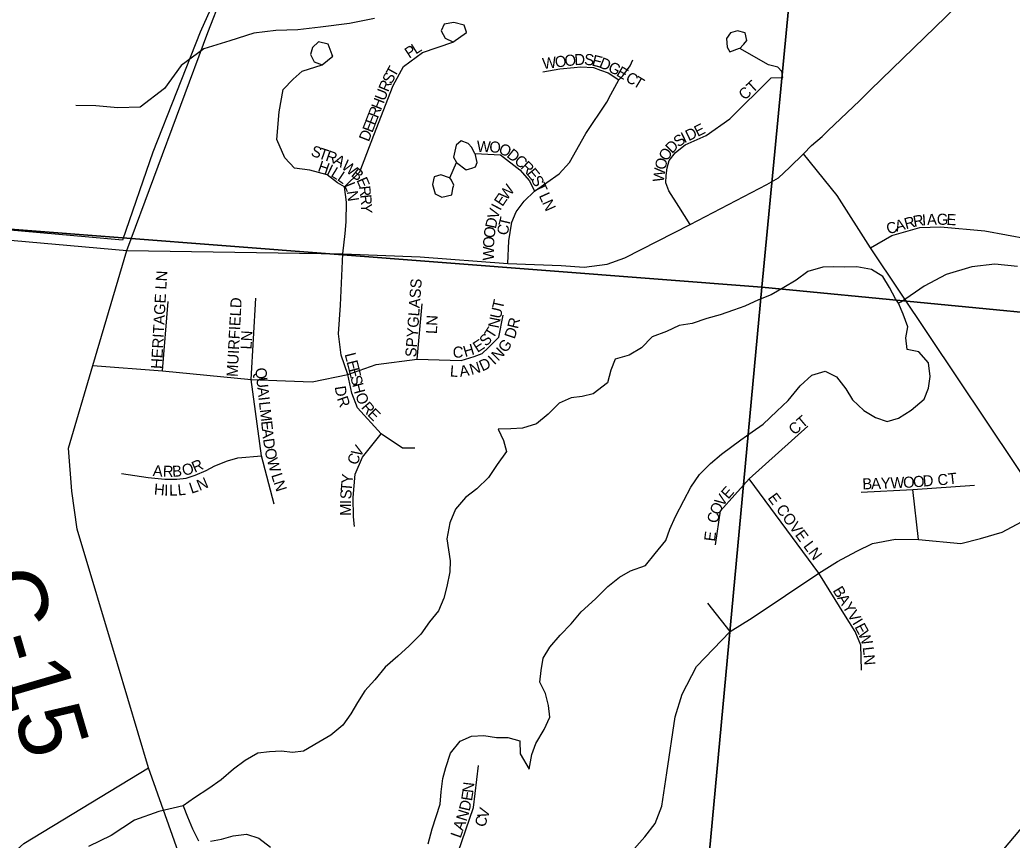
# Model space of a CAD drawing. Extents: x 0 to 1064, y 0 to 440.
# Drawn here: x 172.51 to 186.14, y 107.1 to 118.36 of the extents above; entities that cross this region are included whole.
import ezdxf

# ---------------------------------------------------------------- set-up
doc = ezdxf.new("R2010")
doc.units = 0
for name, color, linetype in [('GM_X_Corporation', 7, 'Continuous'), ('GM_X_County_Road', 7, 'Continuous'), ('GM_X_County_Road_Text', 7, 'Continuous'), ('GM_X_County_Subdivision', 7, 'Continuous'), ('GM_X_Minor_Lake', 7, 'Continuous'), ('GM_X_Minor_River', 7, 'Continuous'), ('GM_X_Section', 7, 'Continuous'), ('GM_X_Township_Road', 7, 'Continuous'), ('GM_X_Township_Subdivision', 7, 'Continuous'), ('GM_X_Township_Subdivision_Text', 7, 'Continuous')]:
    doc.layers.add(name, color=color, linetype=linetype)

msp = doc.modelspace()

# ---------------------------------------------------------------- linework, layer by layer
at = {"layer": 'GM_X_Corporation'}
msp.add_lwpolyline([(176.201, 124.373), (175.606, 119.781), (175.563, 119.506), (175.5, 119.337), (174.988, 118.195), (174.334, 116.544), (173.92, 115.338), (167.075, 115.945), (167.031, 124.73)], dxfattribs=at)
at = {"layer": 'GM_X_County_Road'}
for points in [[(173.981, 115.194), (175.091, 118.189), (175.485, 119.201), (175.565, 119.396)], [(184.2, 117.4), (185.384, 118.549), (185.551, 118.614), (185.847, 118.632), (186.762, 118.52)], [(173.981, 115.194), (176.948, 115.149), (178.012, 115.109), (179.214, 115.015), (179.948, 114.99), (180.263, 114.965), (180.578, 115.008), (180.823, 115.095), (181.719, 115.554), (182.773, 116.1), (182.932, 116.194), (183.084, 116.335), (183.279, 116.523), (183.388, 116.639), (183.533, 116.76), (183.612, 116.837), (183.702, 116.925), (184.045, 117.251), (184.2, 117.4)], [(167.01, 115.771), (170.217, 115.528), (170.761, 115.48), (171.241, 115.437), (173.981, 115.194)], [(173.849, 109.519), (173.297, 111.368), (173.224, 111.89), (173.175, 112.478), (173.513, 113.616), (173.981, 115.194)], [(175.37, 105.001), (174.275, 108.09), (173.849, 109.519)]]:
    msp.add_lwpolyline(points, dxfattribs=at)
at = {"layer": 'GM_X_County_Subdivision'}
msp.add_lwpolyline([(184.113, 102.985), (183.905, 103.57), (183.808, 103.968), (183.917, 104.451), (184.17, 104.765), (186.47, 107.493), (186.741, 108.41), (186.813, 109.014), (186.958, 109.859), (186.958, 110.402), (186.599, 111.646), (184.198, 115.23), (183.742, 115.95), (183.279, 116.523)], dxfattribs=at)
at = {"layer": 'GM_X_Minor_Lake'}
for points in [[(184.582, 114.473), (184.54, 114.533), (184.461, 114.685), (184.369, 114.837), (184.211, 114.934), (184.011, 114.971), (183.847, 114.965), (183.695, 114.971), (183.543, 114.965), (183.336, 114.904), (183.178, 114.788), (183.008, 114.685), (182.831, 114.588), (182.661, 114.515), (182.473, 114.43), (182.315, 114.375), (182.132, 114.309), (181.95, 114.26), (181.749, 114.193), (181.567, 114.163), (181.397, 114.084), (181.196, 114.011), (181.05, 113.859), (180.88, 113.756), (180.691, 113.701), (180.631, 113.549), (180.582, 113.379), (180.388, 113.227), (180.236, 113.191), (180.084, 113.173), (179.919, 113.1), (179.767, 112.948), (179.609, 112.814), (179.415, 112.754), (179.257, 112.747), (179.08, 112.741), (179.153, 112.583), (179.196, 112.432), (179.068, 112.255), (178.947, 112.079), (178.789, 111.921), (178.631, 111.8), (178.497, 111.642), (178.418, 111.454), (178.376, 111.235), (178.424, 110.931), (178.418, 110.779), (178.376, 110.579), (178.333, 110.421), (178.26, 110.245), (178.139, 110.093), (178.017, 109.923), (177.859, 109.765), (177.701, 109.625), (177.531, 109.473), (177.385, 109.297), (177.251, 109.145), (177.148, 108.987), (177.057, 108.829), (176.947, 108.677), (176.783, 108.538), (176.619, 108.44), (176.406, 108.319), (176.254, 108.301), (176.102, 108.319), (175.938, 108.307), (175.78, 108.289), (175.604, 108.191), (175.446, 108.07), (175.276, 107.924), (175.105, 107.803), (174.911, 107.675), (174.753, 107.566), (174.814, 107.414)], [(178.121, 107.043), (178.176, 107.25), (178.285, 107.59), (178.297, 107.76), (178.322, 107.942), (178.364, 108.094), (178.425, 108.289), (178.559, 108.453), (178.717, 108.525), (178.887, 108.532), (179.057, 108.507), (179.215, 108.507), (179.379, 108.459), (179.386, 108.282), (179.507, 108.07), (179.544, 108.27), (179.598, 108.422), (179.714, 108.617), (179.793, 108.787), (179.775, 108.945), (179.732, 109.109), (179.653, 109.267), (179.671, 109.425), (179.701, 109.595), (179.793, 109.746), (179.932, 109.911), (180.084, 110.068), (180.224, 110.232), (180.419, 110.409), (180.589, 110.579), (180.747, 110.706), (180.899, 110.797), (181.106, 110.87), (181.239, 111.034), (181.385, 111.211), (181.44, 111.368), (181.519, 111.539), (181.634, 111.763), (181.731, 111.946), (181.847, 112.116), (181.999, 112.267), (182.151, 112.395), (182.418, 112.596), (182.57, 112.705), (182.722, 112.808), (182.911, 112.99), (183.069, 113.136), (183.233, 113.337), (183.391, 113.482), (183.573, 113.537), (183.731, 113.458), (183.859, 113.294), (183.95, 113.142), (184.108, 112.996), (184.267, 112.899), (184.425, 112.845), (184.583, 112.893), (184.759, 113.002), (184.935, 113.154), (184.996, 113.306), (185.02, 113.464), (184.996, 113.652), (184.862, 113.804), (184.704, 113.835), (184.686, 113.993), (184.71, 114.145), (184.649, 114.321), (184.582, 114.473)], [(174.814, 107.414), (174.881, 107.25), (174.966, 107.086)], [(175.13, 107.08), (175.282, 107.11), (175.44, 107.153), (175.622, 107.177), (175.793, 107.122), (175.951, 107.001)]]:
    msp.add_lwpolyline(points, dxfattribs=at)
at = {"layer": 'GM_X_Minor_River'}
for points in [[(177.383, 118.379), (177.037, 118.312), (176.641, 118.263), (176.331, 118.227), (176.027, 118.215), (175.723, 118.178), (175.395, 118.075), (175.036, 117.966), (174.726, 117.735), (174.495, 117.419), (174.161, 117.164), (173.857, 117.152), (173.553, 117.182), (173.28, 117.188)], [(186.218, 114.977), (185.908, 115.007), (185.592, 114.971), (185.239, 114.867), (184.935, 114.703), (184.625, 114.491), (184.582, 114.473)], [(174.753, 107.566), (174.419, 107.487), (174.084, 107.371), (173.762, 107.159), (173.452, 107.007)]]:
    msp.add_lwpolyline(points, dxfattribs=at)
at = {"layer": 'GM_X_Section'}
for points in [[(168.142, 132.406), (184.27, 131.039), (182.704, 114.691), (166.556, 115.937)], [(184.27, 131.039), (200.029, 129.432), (198.641, 113.153), (182.704, 114.691)], [(166.556, 115.937), (182.704, 114.691), (180.995, 96.285), (164.917, 99.233)]]:
    msp.add_lwpolyline(points, close=True, dxfattribs=at)
msp.add_lwpolyline([(196.734, 94.569), (180.995, 96.285), (182.704, 114.691), (198.641, 113.153)], dxfattribs=at)
at = {"layer": 'GM_X_Township_Road'}
msp.add_lwpolyline([(167.948, 105.244), (168.32, 105.412), (169.431, 105.913), (170.031, 106.261), (170.509, 106.374), (171.357, 106.524), (171.637, 106.492), (171.819, 106.52), (172.115, 106.652), (172.565, 107.051), (174.275, 108.09)], dxfattribs=at)
at = {"layer": 'GM_X_Township_Subdivision'}
for points in [[(178.645, 118.192), (178.616, 118.291), (178.473, 118.327), (178.34, 118.305), (178.299, 118.213), (178.355, 118.113), (178.457, 118.061)], [(176.971, 116.07), (177.181, 116.276), (177.371, 116.779), (177.639, 117.459), (177.783, 117.723), (178.043, 117.913), (178.46, 118.058), (178.646, 118.187), (178.645, 118.192)], [(182.448, 118.021), (182.456, 118.03), (182.498, 118.078), (182.474, 118.184), (182.371, 118.211), (182.273, 118.185), (182.219, 118.107), (182.227, 117.986), (182.267, 117.925), (182.4, 117.972)], [(176.802, 117.879), (176.801, 117.882), (176.747, 118.027), (176.612, 118.059), (176.529, 117.981), (176.501, 117.886), (176.551, 117.785), (176.661, 117.745)], [(181.719, 115.554), (181.566, 115.797), (181.427, 116.012), (181.384, 116.123), (181.39, 116.226), (181.404, 116.328), (181.43, 116.431), (181.519, 116.539), (181.651, 116.646), (181.938, 116.775), (182.266, 117.003), (182.832, 117.566), (182.994, 117.569), (182.978, 117.655), (182.924, 117.715), (182.797, 117.744), (182.403, 117.969), (182.448, 118.021)], [(176.948, 115.149), (176.977, 115.427), (176.995, 115.59), (176.999, 115.858), (176.971, 116.07), (176.872, 116.123), (176.731, 116.235), (176.492, 116.296), (176.282, 116.325), (176.152, 116.468), (176.039, 116.717), (176.072, 117.097), (176.125, 117.406), (176.266, 117.546), (176.389, 117.657), (176.664, 117.745), (176.808, 117.863), (176.802, 117.879)], [(179.695, 117.648), (179.93, 117.688), (180.127, 117.708)], [(180.127, 117.708), (180.214, 117.717), (180.391, 117.706), (180.489, 117.67), (180.592, 117.636), (180.738, 117.538)], [(180.631, 117.338), (180.738, 117.538), (180.793, 117.596), (180.896, 117.73), (180.93, 117.813)], [(179.214, 115.015), (179.229, 115.326), (179.268, 115.583), (179.33, 115.728), (179.438, 115.872), (179.583, 116.01), (179.919, 116.248), (180.06, 116.404), (180.288, 116.8), (180.574, 117.23), (180.631, 117.338)], [(178.672, 116.662), (178.671, 116.663), (178.572, 116.7), (178.504, 116.641), (178.469, 116.478), (178.509, 116.405), (178.641, 116.303), (178.686, 116.317)], [(178.762, 116.525), (178.716, 116.614), (178.672, 116.662)], [(178.686, 116.317), (178.721, 116.327), (178.769, 116.342), (178.795, 116.402), (178.765, 116.525), (179.114, 116.509), (179.379, 116.303), (179.512, 116.153), (179.583, 116.01)], [(178.461, 116.047), (178.461, 116.05), (178.471, 116.094), (178.442, 116.162), (178.416, 116.193), (178.509, 116.405)], [(178.413, 116.193), (178.292, 116.233), (178.2, 116.205), (178.179, 116.102), (178.218, 115.973), (178.308, 115.928), (178.443, 115.961), (178.461, 116.047)], [(184.198, 115.23), (184.492, 115.399), (184.874, 115.509), (185.16, 115.519), (185.771, 115.465), (186.365, 115.355), (186.562, 115.333), (186.734, 115.369), (186.91, 115.502), (187.28, 115.664), (187.415, 115.719), (187.586, 115.744), (187.983, 115.792), (188.366, 115.815), (188.725, 115.818), (189.012, 115.796), (189.38, 115.686), (189.833, 115.411), (190.245, 115.132), (190.498, 114.875), (190.638, 114.676), (190.843, 114.542), (191.143, 114.451), (192.172, 114.458)], [(177.936, 112.479), (177.769, 112.479), (177.472, 112.678), (177.148, 113.032), (177.07, 113.236), (177.018, 113.492), (176.924, 113.758), (176.887, 114.05), (176.913, 114.442), (176.948, 115.149)], [(174.471, 113.544), (174.548, 114.496)], [(175.687, 113.424), (175.751, 114.541)], [(177.968, 113.701), (178.037, 114.462)], [(173.513, 113.616), (174.471, 113.544), (175.687, 113.424), (176.158, 113.404), (176.527, 113.393), (177.018, 113.492), (177.404, 113.627), (177.968, 113.701), (178.573, 113.685), (178.75, 113.737), (178.86, 113.779), (178.944, 113.857), (179.091, 114.002), (179.152, 114.306)], [(176.005, 111.712), (175.828, 112.375), (175.687, 113.424)], [(182.07, 111.15), (182.137, 111.621), (182.529, 112.057), (183.337, 112.78)], [(177.108, 111.403), (177.092, 111.538), (177.091, 111.801), (177.117, 112.124), (177.216, 112.354), (177.472, 112.678)], [(173.907, 112.132), (174.274, 112.077), (174.499, 112.056), (174.667, 112.055), (174.794, 112.067), (174.919, 112.109), (175.067, 112.174), (175.189, 112.237), (175.363, 112.307), (175.505, 112.347), (175.828, 112.375)], [(183.486, 110.765), (182.529, 112.057)], [(184.072, 111.875), (184.78, 111.912), (185.628, 111.973)], [(184.859, 111.227), (184.78, 111.912)], [(180.881, 106.897), (181.097, 107.139), (181.238, 107.325), (181.329, 107.561), (181.399, 108.019), (181.515, 108.788), (181.61, 109.1), (181.806, 109.483), (182.269, 109.96), (182.571, 110.151), (183.486, 110.765), (183.743, 110.921), (184.009, 111.067), (184.226, 111.172), (184.542, 111.228), (184.859, 111.227), (185.438, 111.172), (185.709, 111.238), (186.006, 111.328), (186.273, 111.469)], [(183.856, 110.174), (183.486, 110.765)], [(182.269, 109.96), (181.961, 110.35)], [(184.075, 109.431), (184.064, 109.772), (183.989, 109.961), (183.856, 110.174)], [(178.537, 106.308), (178.531, 106.931), (178.742, 107.542), (178.813, 108.123)]]:
    msp.add_lwpolyline(points, dxfattribs=at)

# ---------------------------------------------------------------- texts
at = {"layer": 'GM_X_County_Road_Text'}
msp.add_text('C-15', height=0.9091, rotation=286.3705, dxfattribs=at).set_placement((171.868, 110.691))
at = {"layer": 'GM_X_Township_Subdivision_Text'}
for s, height, rotation, p in [('P', 0.152, 33.4476, (177.86, 117.827)), ('L', 0.152, 32.3036, (177.949, 117.885)), ('W', 0.152, 7.1125, (179.699, 117.685)), ('O', 0.152, 7.1006, (179.871, 117.706)), ('O', 0.152, 7.0973, (180.003, 117.723)), ('D', 0.152, 3.0829, (180.133, 117.739)), ('S', 0.152, 355.1048, (180.26, 117.746)), ('E', 0.152, 345.586, (180.36, 117.738)), ('D', 0.152, 338.0443, (180.458, 117.713)), ('T', 0.152, 61.0515, (177.664, 117.564)), ('G', 0.152, 331.9198, (180.578, 117.665)), ('E', 0.152, 329.4486, (180.694, 117.603)), ('S', 0.152, 62.384, (177.615, 117.47)), ('C', 0.152, 329.0321, (180.82, 117.529)), ('T', 0.152, 329.0316, (180.923, 117.467)), ('U', 0.152, 68.6665, (177.521, 117.239)), ('R', 0.152, 67.2382, (177.57, 117.363)), ('CT', 0.1515, 42.7108, (182.47, 117.251)), ('H', 0.152, 68.6612, (177.473, 117.115)), ('R', 0.152, 68.6766, (177.429, 117.003)), ('E', 0.152, 68.6703, (177.39, 116.904)), ('E', 0.152, 68.6751, (177.352, 116.804)), ('D', 0.152, 25.4117, (181.699, 116.695)), ('E', 0.152, 26.4436, (181.822, 116.753)), ('D', 0.152, 68.6612, (177.303, 116.68)), ('S', 0.152, 35.7663, (181.559, 116.607)), ('I', 0.152, 26.174, (181.64, 116.666)), ('S', 0.152, 341.3146, (176.498, 116.499)), ('T', 0.152, 341.302, (176.599, 116.465)), ('W', 0.152, 357.2753, (178.784, 116.552)), ('O', 0.152, 356.8287, (178.957, 116.544)), ('O', 0.152, 334.7058, (179.075, 116.54)), ('D', 0.152, 321.4119, (179.188, 116.488)), ('O', 0.152, 58.0989, (181.403, 116.412)), ('D', 0.152, 44.227, (181.468, 116.518)), ('R', 0.152, 341.3128, (176.7, 116.431)), ('A', 0.152, 329.7672, (176.807, 116.396)), ('C', 0.152, 320.6081, (179.291, 116.405)), ('O', 0.152, 76.7908, (181.378, 116.294)), ('H', 0.152, 340.8255, (176.593, 116.289)), ('I', 0.152, 334.3149, (176.714, 116.247)), ('L', 0.152, 328.5536, (176.771, 116.22)), ('W', 0.152, 320.8123, (176.917, 116.332)), ('B', 0.152, 320.8131, (177.051, 116.223)), ('R', 0.152, 315.1718, (179.381, 116.332)), ('E', 0.152, 309.176, (179.464, 116.25)), ('W', 0.152, 82.0554, (181.355, 116.126)), ('L', 0.152, 325.6659, (176.86, 116.166)), ('E', 0.152, 293.1663, (177.132, 116.162)), ('S', 0.152, 298.3859, (179.527, 116.174)), ('L', 0.152, 291.5376, (176.962, 116.096)), ('R', 0.152, 276.1069, (177.171, 116.076)), ('W', 0.152, 51.5897, (179.198, 115.875)), ('T', 0.152, 295.1473, (179.576, 116.082)), ('N', 0.152, 278.4886, (176.999, 116.005)), ('R', 0.152, 276.1257, (177.184, 115.956)), ('E', 0.152, 55.7265, (179.14, 115.79)), ('L', 0.152, 294.2066, (179.638, 115.949)), ('Y', 0.152, 270.6121, (177.197, 115.841)), ('V', 0.152, 73.217, (179.075, 115.614)), ('I', 0.152, 62.1254, (179.111, 115.734)), ('N', 0.152, 294.2438, (179.682, 115.852)), ('D', 0.152, 77.9999, (179.049, 115.487)), ('T', 0.152, 76.686, (179.233, 115.512)), ('R', 0.152, 15.2381, (184.685, 115.486)), ('R', 0.152, 10.4764, (184.798, 115.517)), ('I', 0.152, 3.9362, (184.911, 115.538)), ('A', 0.152, 2.6234, (184.977, 115.543)), ('G', 0.152, 359.0819, (185.108, 115.549)), ('E', 0.152, 356.9657, (185.239, 115.547)), ('O', 0.152, 81.5114, (179.029, 115.357)), ('C', 0.152, 79.8668, (179.212, 115.396)), ('C', 0.152, 18.5348, (184.445, 115.413)), ('A', 0.152, 15.5101, (184.557, 115.451)), ('O', 0.152, 88.4165, (179.026, 115.229)), ('W', 0.152, 88.4028, (179.021, 115.055)), ('HERITAGE LN', 0.15152, 86.8567, (174.461, 113.565)), ('SPYGLASS', 0.1515, 85.8545, (177.955, 113.725)), ('MUIRFIELD', 0.1515, 86.9889, (175.501, 113.456)), ('U', 0.152, 77.3052, (179.116, 114.249)), ('T', 0.152, 77.3082, (179.145, 114.379)), ('LN', 0.1515, 86.989, (178.239, 114.045)), ('N', 0.152, 78.9074, (179.09, 114.119)), ('T', 0.152, 57.7716, (179.011, 113.972)), ('D', 0.152, 71.764, (179.307, 113.971)), ('R', 0.152, 76.5112, (179.352, 114.111)), ('LN', 0.1515, 86.9884, (175.692, 113.833)), ('S', 0.152, 45.9874, (178.916, 113.869)), ('C', 0.152, 358.8829, (178.456, 113.725)), ('H', 0.152, 16.6541, (178.627, 113.729)), ('E', 0.152, 32.9197, (178.797, 113.787)), ('N', 0.152, 45.493, (179.081, 113.667)), ('G', 0.152, 53.6678, (179.189, 113.78)), ('L', 0.152, 284.1622, (176.971, 113.77)), ('I', 0.152, 43.4225, (179.028, 113.617)), ('E', 0.152, 284.1622, (176.997, 113.667)), ('L', 0.152, 355.1592, (178.414, 113.466)), ('A', 0.152, 8.8202, (178.56, 113.458)), ('N', 0.152, 16.7609, (178.714, 113.483)), ('D', 0.152, 25.2154, (178.864, 113.531)), ('Q', 0.152, 276.2701, (175.743, 113.577)), ('E', 0.152, 284.1622, (177.023, 113.563)), ('S', 0.152, 284.1759, (177.049, 113.46)), ('U', 0.152, 276.2701, (175.757, 113.445)), ('D', 0.152, 278.8442, (176.835, 113.323)), ('H', 0.152, 284.66, (177.075, 113.355)), ('A', 0.152, 276.2701, (175.772, 113.312)), ('R', 0.152, 289.0446, (176.863, 113.163)), ('O', 0.152, 290.7159, (177.115, 113.209)), ('I', 0.152, 276.2701, (175.786, 113.18)), ('L', 0.152, 276.2701, (175.794, 113.113)), ('R', 0.152, 310.614, (177.191, 113.036)), ('M', 0.152, 276.2701, (175.805, 113.007)), ('E', 0.152, 315.1714, (177.278, 112.935)), ('CT', 0.1515, 40.2394, (183.151, 112.652)), ('E', 0.152, 276.2701, (175.823, 112.848)), ('A', 0.152, 276.2701, (175.834, 112.742)), ('D', 0.152, 278.1572, (175.85, 112.604)), ('V', 0.152, 57.6193, (177.181, 112.342)), ('O', 0.152, 281.9315, (175.87, 112.462)), ('C', 0.152, 69.0148, (177.142, 112.237)), ('A', 0.152, 355.9751, (174.332, 112.098)), ('R', 0.152, 358.3902, (174.472, 112.089)), ('B', 0.152, 3.0217, (174.605, 112.085)), ('O', 0.152, 15.1657, (174.76, 112.097)), ('R', 0.152, 23.3966, (174.911, 112.14)), ('W', 0.152, 285.7058, (175.901, 112.32)), ('L', 0.152, 287.5929, (175.961, 112.11)), ('Y', 0.152, 85.2509, (177.076, 111.986)), ('O', 0.152, 2.6877, (184.65, 111.933)), ('O', 0.152, 4.7569, (184.789, 111.94)), ('D', 0.152, 5.2218, (184.923, 111.951)), ('CT', 0.1515, 6.3375, (185.127, 111.965)), ('H', 0.152, 354.9006, (174.347, 111.842)), ('I', 0.152, 358.8439, (174.491, 111.829)), ('L', 0.152, 0.4008, (174.562, 111.828)), ('L', 0.152, 5.6906, (174.684, 111.829)), ('L', 0.152, 18.264, (174.865, 111.853)), ('N', 0.152, 22.6558, (174.978, 111.891)), ('N', 0.152, 287.5929, (175.993, 112.009)), ('T', 0.152, 85.3498, (177.068, 111.88)), ('E', 0.152, 48.1721, (182.243, 111.771)), ('B', 0.152, 2.2101, (184.089, 111.912)), ('A', 0.152, 2.2249, (184.209, 111.916)), ('Y', 0.152, 2.2085, (184.342, 111.922)), ('W', 0.152, 2.2206, (184.475, 111.927)), ('S', 0.152, 86.9657, (177.062, 111.775)), ('V', 0.152, 54.4107, (182.168, 111.666)), ('E COVE LN', 0.1515, 306.5526, (182.779, 111.794)), ('I', 0.152, 89.3445, (177.061, 111.71)), ('M', 0.152, 89.9089, (177.061, 111.55)), ('O', 0.152, 66.888, (182.12, 111.551)), ('C', 0.152, 79.3652, (182.101, 111.442)), ('E', 0.152, 82.8783, (182.061, 111.193)), ('B', 0.152, 301.1429, (183.674, 110.525)), ('A', 0.152, 301.1249, (183.736, 110.422)), ('Y', 0.152, 301.1384, (183.805, 110.308)), ('V', 0.152, 301.1437, (183.874, 110.194)), ('I', 0.152, 301.1437, (183.943, 110.08)), ('E', 0.152, 297.9825, (183.976, 110.025)), ('W', 0.152, 291.3768, (184.024, 109.935)), ('L', 0.152, 276.7354, (184.09, 109.744)), ('N', 0.152, 274.5948, (184.103, 109.639)), ('N', 0.152, 83.1614, (178.738, 107.739)), ('E', 0.152, 81.0606, (178.721, 107.627)), ('D', 0.152, 76.859, (178.688, 107.485)), ('N', 0.152, 72.6574, (178.645, 107.346)), ('V', 0.152, 73.0892, (178.936, 107.381)), ('A', 0.152, 70.5566, (178.599, 107.215)), ('C', 0.152, 71.6188, (178.897, 107.263)), ('L', 0.152, 70.5566, (178.564, 107.114))]:
    msp.add_text(s, height=height, rotation=rotation, dxfattribs=at).set_placement(p)

doc.saveas('drawing.dxf')
